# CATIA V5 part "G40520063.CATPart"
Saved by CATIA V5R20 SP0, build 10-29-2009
Part number: G40520063
Revision: 8
Definition: design
Nomenclature: G40520063
Source: made
Description: NOT SPECIFIED
Bounding box of the stored display mesh (mm): x -31.5 to 31.5, y -10 to 10, z -20 to 0
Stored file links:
  C:\Users\Raffaele\Desktop\3D X SITO CF\BOLEX\29-GUIDE STRIP REF 405\G40520063.CATPart
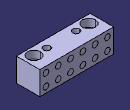
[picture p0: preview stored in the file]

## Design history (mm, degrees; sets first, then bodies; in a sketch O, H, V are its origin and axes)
Body1 "MANIFOLD_SOLID_BREP #2374" (main body)
  Solid1: solid without history
Body2 "MANIFOLD_SOLID_BREP #2512"
  Solid2: solid without history
Body3 "MANIFOLD_SOLID_BREP #2624"
  Solid3: solid without history
Body4 "MANIFOLD_SOLID_BREP #2736"
  Solid4: solid without history
Body5 "MANIFOLD_SOLID_BREP #2848"
  Solid5: solid without history
Body6 "MANIFOLD_SOLID_BREP #2960"
  Solid6: solid without history
Body7 "MANIFOLD_SOLID_BREP #3072"
  Solid7: solid without history
Body8 "MANIFOLD_SOLID_BREP #3210"
  Solid8: solid without history
Body9 "MANIFOLD_SOLID_BREP #3348"
  Solid9: solid without history
Body10 "MANIFOLD_SOLID_BREP #3486"
  Solid10: solid without history
Body11 "MANIFOLD_SOLID_BREP #3624"
  Solid11: solid without history
Body12 "MANIFOLD_SOLID_BREP #3736"
  Solid12: solid without history
Body13 "MANIFOLD_SOLID_BREP #3848"
  Solid13: solid without history
Body14 "MANIFOLD_SOLID_BREP #3960"
  Solid14: solid without history
Body15 "MANIFOLD_SOLID_BREP #4072"
  Solid15: solid without history
Body16 "MANIFOLD_SOLID_BREP #4184"
  Solid16: solid without history
Body17 "MANIFOLD_SOLID_BREP #4296"
  Solid17: solid without history
Body18 "MANIFOLD_SOLID_BREP #4408"
  Solid18: solid without history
